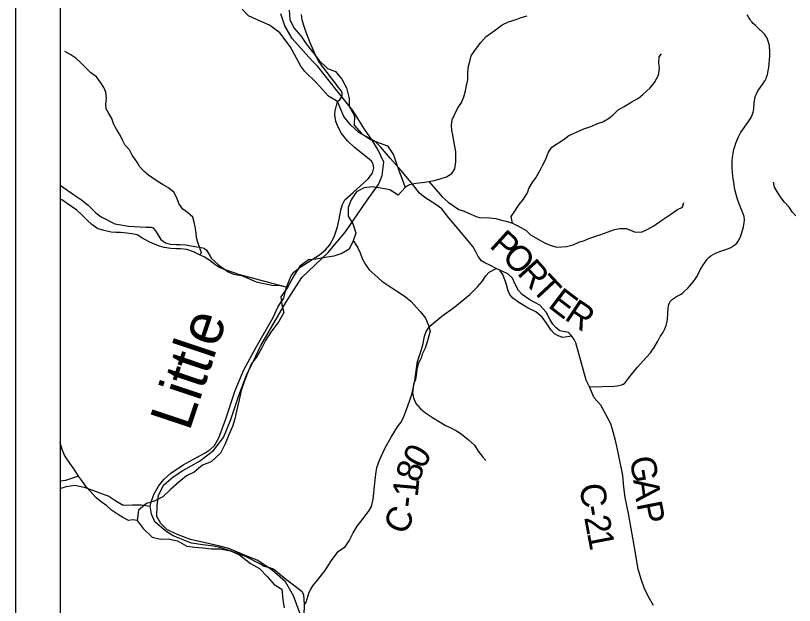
# Model space of a CAD drawing. Extents: x 0 to 34, y 0 to 22.
# Drawn here: x 2 to 3.746, y 17.398 to 18.72 of the extents above; entities that cross this region are included whole.
import ezdxf

# ---------------------------------------------------------------- set-up
doc = ezdxf.new("R2010")
doc.units = 0
for name, color, linetype in [('GM_X_County_Road', 7, 'Continuous'), ('GM_X_County_Road_Text', 7, 'Continuous'), ('GM_X_Minor_River', 7, 'Continuous'), ('GM_X_Minor_River_Text', 7, 'Continuous'), ('GM_X_Rail_Line', 7, 'Continuous'), ('GM_X_Township_Road', 7, 'Continuous'), ('SH_Data', 7, 'Continuous')]:
    doc.layers.add(name, color=color, linetype=linetype)

msp = doc.modelspace()

# ---------------------------------------------------------------- linework, layer by layer
at = {"layer": 'GM_X_County_Road'}
for points in [[(2.7215, 18.5278), (2.7014, 18.5397), (2.6747, 18.5691), (2.6483, 18.5951), (2.6393, 18.6066), (2.6157, 18.6508), (2.5928, 18.6813), (2.569, 18.6989), (2.5402, 18.7113), (2.5221, 18.7197), (2.5078, 18.7347)], [(3.2864, 17.8884), (3.3149, 17.889), (3.3412, 17.8899), (3.3491, 17.8903), (3.3554, 17.8916), (3.3585, 17.8924), (3.3622, 17.894), (3.3658, 17.8968), (3.3704, 17.9024), (3.3751, 17.9086), (3.3935, 17.9312), (3.4144, 17.9544), (3.4234, 17.9642), (3.4257, 17.9679), (3.4316, 17.9762), (3.4397, 17.9902), (3.4453, 18.0012), (3.4457, 18.0018), (3.4511, 18.0093), (3.4556, 18.0184), (3.4586, 18.0256), (3.4604, 18.0319), (3.4611, 18.0355), (3.4615, 18.0383), (3.4626, 18.0533), (3.4633, 18.0643), (3.4637, 18.0689), (3.4645, 18.0729), (3.4658, 18.0766), (3.4677, 18.0791), (3.4699, 18.0819), (3.4732, 18.0847), (3.4821, 18.0903), (3.4921, 18.0959), (3.4963, 18.0992), (3.5008, 18.1031), (3.5069, 18.1094), (3.5128, 18.1156), (3.5189, 18.1232), (3.5237, 18.1295), (3.5278, 18.1363), (3.5357, 18.152), (3.5384, 18.1563), (3.5393, 18.1578), (3.5475, 18.17), (3.5508, 18.1742), (3.5545, 18.1779), (3.5591, 18.1819), (3.5639, 18.1849), (3.5694, 18.1877), (3.5792, 18.1917), (3.5948, 18.197), (3.6037, 18.2007), (3.6129, 18.2063), (3.6172, 18.2102), (3.6202, 18.2145), (3.6227, 18.2198), (3.6259, 18.2266), (3.6323, 18.2464), (3.6338, 18.2562), (3.6341, 18.2626), (3.6332, 18.2699), (3.6315, 18.2756), (3.6281, 18.2834), (3.6238, 18.2943), (3.6206, 18.3022), (3.618, 18.3106), (3.6157, 18.3191), (3.6136, 18.3277), (3.6121, 18.3345), (3.6102, 18.3467), (3.6091, 18.3546), (3.6082, 18.3606), (3.6073, 18.3693), (3.6065, 18.3779), (3.6065, 18.3878), (3.6069, 18.3943), (3.6076, 18.402), (3.6087, 18.4113), (3.6104, 18.4209), (3.6123, 18.4266), (3.6149, 18.4345), (3.6207, 18.4485), (3.6263, 18.4589), (3.6288, 18.4626), (3.6345, 18.4703), (3.6381, 18.475), (3.6419, 18.4802), (3.6462, 18.4869), (3.649, 18.4914), (3.6508, 18.4952), (3.6522, 18.499), (3.6534, 18.5034), (3.6544, 18.507), (3.655, 18.5121), (3.6559, 18.5243), (3.6564, 18.5282), (3.6573, 18.5336), (3.6583, 18.5377), (3.6598, 18.5419), (3.6609, 18.5445), (3.6644, 18.5511), (3.6758, 18.5676), (3.6762, 18.5682), (3.6799, 18.5737), (3.6806, 18.5746), (3.6826, 18.5788), (3.6837, 18.5821), (3.6855, 18.5882), (3.6871, 18.5965), (3.6886, 18.6038), (3.6896, 18.612), (3.6905, 18.6206), (3.6912, 18.6294), (3.6912, 18.6338), (3.6912, 18.6388), (3.6912, 18.6428), (3.6906, 18.6481), (3.69, 18.6528), (3.6896, 18.6551), (3.6882, 18.6606), (3.6862, 18.6671), (3.6842, 18.6708), (3.6823, 18.6738), (3.6795, 18.6777), (3.6763, 18.6814), (3.6715, 18.6859), (3.6703, 18.6869), (3.6587, 18.698), (3.6538, 18.7024), (3.6505, 18.706), (3.6485, 18.7085), (3.6467, 18.7111), (3.6442, 18.715), (3.6422, 18.7185), (3.6403, 18.7218)], [(2.6481, 17.4006), (2.6461, 17.4224), (2.6425, 17.4286), (2.6045, 17.458), (2.5917, 17.4685), (2.5819, 17.4769), (2.576, 17.4805), (2.5701, 17.4823), (2.5635, 17.4842), (2.5572, 17.4855), (2.5488, 17.4906), (2.5156, 17.508), (2.4814, 17.5208), (2.4579, 17.5283), (2.444, 17.531), (2.4199, 17.5342), (2.3948, 17.5379), (2.3536, 17.5545), (2.3371, 17.5647), (2.3125, 17.5855), (2.305, 17.6026), (2.3014, 17.6208), (2.3038, 17.6295), (2.3101, 17.6469), (2.3202, 17.6654), (2.3322, 17.6804), (2.3483, 17.695), (2.3758, 17.7136), (2.4247, 17.7402), (2.4366, 17.748), (2.4462, 17.757), (2.4556, 17.7743), (2.4706, 17.8143), (2.4927, 17.8797), (2.5116, 17.9266), (2.5397, 17.9774), (2.5778, 18.0434), (2.588, 18.0668), (2.593, 18.075), (2.6012, 18.0871), (2.6072, 18.1113), (2.6127, 18.1241), (2.6178, 18.1366), (2.624, 18.1452), (2.6382, 18.1564), (2.6814, 18.1839), (2.6948, 18.1955), (2.7045, 18.2067), (2.7146, 18.2241), (2.7221, 18.2464), (2.7258, 18.2642), (2.7291, 18.2842), (2.7327, 18.2964), (2.7385, 18.3069), (2.7566, 18.3233), (2.7904, 18.3544), (2.8001, 18.3672), (2.8036, 18.3789), (2.8019, 18.3873), (2.7978, 18.3938), (2.7888, 18.4011), (2.7596, 18.4243), (2.7443, 18.4394), (2.7309, 18.4555), (2.7243, 18.4685), (2.7181, 18.4827), (2.7156, 18.4975), (2.7165, 18.507), (2.7215, 18.5278)], [(3.0775, 18.1536), (3.0633, 18.1605), (3.0521, 18.1661), (3.0443, 18.1709), (3.037, 18.1802), (3.032, 18.1906), (3.0251, 18.2026), (3.0075, 18.224), (2.9709, 18.2677), (2.9555, 18.2867), (2.9425, 18.297), (2.9176, 18.3122), (2.9054, 18.322), (2.89, 18.3426), (2.8647, 18.3726), (2.8398, 18.4003), (2.8189, 18.4256), (2.8056, 18.4385), (2.7847, 18.4498), (2.7694, 18.4579), (2.7506, 18.4751), (2.736, 18.4942), (2.7215, 18.5278)], [(2.6481, 17.4006), (2.6518, 17.4055), (2.6586, 17.4281), (2.6613, 17.4334), (2.6667, 17.4425), (2.677, 17.4548), (2.6944, 17.4765), (2.7, 17.4866), (2.7096, 17.5016), (2.7241, 17.5198), (2.7388, 17.5299), (2.7479, 17.5433), (2.7568, 17.5612), (2.7659, 17.5758), (2.7793, 17.5932), (2.7927, 17.6115), (2.7983, 17.6204), (2.8018, 17.6366), (2.8051, 17.6726), (2.8076, 17.6923), (2.8103, 17.7078), (2.8157, 17.7236), (2.8278, 17.7502), (2.8422, 17.7753), (2.8565, 17.7984), (2.8636, 17.8081), (2.8696, 17.8197), (2.8745, 17.8317), (2.8795, 17.8456), (2.8881, 17.8708), (2.8951, 17.9014), (2.8986, 17.9294), (2.9013, 17.9449), (2.9104, 17.972), (2.9138, 17.9855), (2.9166, 18.0018), (2.9203, 18.0123), (2.929, 18.0242), (2.9558, 18.0466), (2.9852, 18.0678), (3.0186, 18.0953), (3.0354, 18.1123), (3.0463, 18.1241), (3.0547, 18.1371), (3.0617, 18.1453), (3.0775, 18.1536)], [(3.4305, 17.3981), (3.419, 17.4174), (3.4093, 17.4378), (3.4034, 17.4551), (3.3962, 17.48), (3.3864, 17.5373), (3.374, 17.6045), (3.3667, 17.6404), (3.3639, 17.6633), (3.3616, 17.6892), (3.3509, 17.741), (3.3455, 17.7651), (3.3401, 17.7877), (3.3347, 17.8054), (3.3224, 17.8278), (3.3118, 17.8468), (3.297, 17.8635), (3.2864, 17.8884), (3.2796, 17.9031), (3.267, 17.9465), (3.2587, 17.9785), (3.256, 17.9866), (3.2523, 17.9945), (3.2474, 18.0021), (3.2269, 17.9987), (3.2168, 18.0024), (3.2082, 18.0069), (3.2005, 18.0154), (3.1903, 18.0306), (3.1805, 18.0441), (3.1668, 18.0559), (3.1496, 18.0648), (3.128, 18.0772), (3.1146, 18.0867), (3.108, 18.0949), (3.1045, 18.1034), (3.0996, 18.1199), (3.0923, 18.1398), (3.0857, 18.1499), (3.0775, 18.1536)], [(2.8377, 17.269), (2.8253, 17.2752), (2.8084, 17.2794), (2.7953, 17.2811), (2.7819, 17.2814), (2.7647, 17.2797), (2.7557, 17.2787), (2.7306, 17.2752), (2.7127, 17.2735), (2.699, 17.2763), (2.6893, 17.2835), (2.6804, 17.2931), (2.6683, 17.3104), (2.6579, 17.3275), (2.654, 17.3383), (2.6469, 17.3614), (2.6466, 17.3675), (2.6469, 17.3761), (2.6481, 17.4006)]]:
    msp.add_lwpolyline(points, dxfattribs=at)
at = {"layer": 'GM_X_Minor_River'}
for points in [[(2.6132, 18.7321), (2.615, 18.7116), (2.6237, 18.6925), (2.6395, 18.6746), (2.6516, 18.6568), (2.6659, 18.6385), (2.681, 18.6191), (2.6992, 18.6015), (2.717, 18.5947), (2.7313, 18.5776), (2.7419, 18.5581), (2.7482, 18.5345), (2.7478, 18.517), (2.7599, 18.4957), (2.7595, 18.4748), (2.7757, 18.4561), (2.7957, 18.4424), (2.8154, 18.4352), (2.8339, 18.4279), (2.8471, 18.4077), (2.8535, 18.3902), (2.8592, 18.3727), (2.8671, 18.3537), (2.8735, 18.3347), (2.8579, 18.3176), (2.8394, 18.3294), (2.8189, 18.3332), (2.8, 18.3366), (2.7815, 18.3344), (2.7644, 18.3249), (2.7523, 18.307), (2.7454, 18.2899), (2.7457, 18.2708), (2.7567, 18.2518), (2.7627, 18.2324), (2.757, 18.2153), (2.7482, 18.1966), (2.7312, 18.1871), (2.7137, 18.1807), (2.694, 18.178), (2.6743, 18.1742), (2.6569, 18.1727), (2.6372, 18.1583), (2.6239, 18.137), (2.6098, 18.1108), (2.5947, 18.0898), (2.5973, 18.0723), (2.6018, 18.0548), (2.5904, 18.0347), (2.5725, 18.0107), (2.56, 17.9924), (2.5512, 17.9742), (2.5417, 17.9567), (2.5284, 17.9388), (2.5201, 17.9187), (2.5128, 17.8996), (2.506, 17.8802), (2.501, 17.8593), (2.4953, 17.8334), (2.4918, 17.8163), (2.4861, 17.7992), (2.4785, 17.7806), (2.4701, 17.7604), (2.4595, 17.7399), (2.4386, 17.7201), (2.4193, 17.7125), (2.4003, 17.6973), (2.3832, 17.6889), (2.3662, 17.6745), (2.3476, 17.6585), (2.3301, 17.6414), (2.3108, 17.6323), (2.2938, 17.6266), (2.2759, 17.6122), (2.2729, 17.589), (2.2857, 17.5711), (2.3061, 17.5516), (2.3246, 17.547), (2.3424, 17.5474)], [(2.8735, 18.3347), (2.8743, 18.3367), (2.8841, 18.3416), (2.8974, 18.3446), (2.9113, 18.3462), (2.9268, 18.3481), (2.9382, 18.3507), (2.9522, 18.3542), (2.9658, 18.3591), (2.9783, 18.3663), (2.9851, 18.377), (2.987, 18.3925), (2.9873, 18.4039), (2.987, 18.4149), (2.9851, 18.4274), (2.9824, 18.4388), (2.9802, 18.4525), (2.9779, 18.4635), (2.9771, 18.4737), (2.9787, 18.4863), (2.9836, 18.4961), (2.9911, 18.5121), (2.9995, 18.525), (3.0048, 18.5379), (3.0085, 18.5512), (3.0112, 18.5633), (3.0138, 18.5762), (3.0142, 18.5922), (3.0157, 18.6066), (3.0191, 18.6202), (3.0218, 18.6297), (3.0312, 18.6438), (3.0433, 18.6601), (3.0551, 18.6734), (3.0679, 18.6818), (3.0811, 18.692), (3.0913, 18.6992), (3.105, 18.7061), (3.122, 18.711), (3.1337, 18.7156), (3.1469, 18.7198)], [(2.4127, 18.1842), (2.4169, 18.1887), (2.4127, 18.2016), (2.4086, 18.2119), (2.4055, 18.2229), (2.4048, 18.2331), (2.4025, 18.2468), (2.4006, 18.2571), (2.3972, 18.2681), (2.3851, 18.2791), (2.3753, 18.2866), (2.3662, 18.2992), (2.3617, 18.3117), (2.3549, 18.3242), (2.3417, 18.3352), (2.3311, 18.3405), (2.3198, 18.3473), (2.308, 18.3557), (2.2982, 18.3625), (2.2873, 18.3716), (2.2789, 18.3815), (2.2725, 18.3917), (2.2616, 18.4073), (2.2555, 18.4194), (2.2449, 18.4308), (2.2396, 18.441), (2.2343, 18.4524), (2.2272, 18.4642), (2.2204, 18.4763), (2.2155, 18.4892), (2.209, 18.501), (2.2034, 18.5108), (2.2022, 18.5207), (2.2037, 18.5351), (2.2022, 18.5484), (2.1981, 18.559), (2.1913, 18.5693), (2.1818, 18.5829), (2.169, 18.592), (2.1584, 18.6019), (2.1452, 18.6148), (2.135, 18.6246), (2.1236, 18.6318), (2.1108, 18.6398)], [(3.1143, 18.2552), (3.1109, 18.2696), (3.1181, 18.2795), (3.1287, 18.297), (3.1385, 18.3084), (3.1476, 18.3228), (3.1506, 18.3323), (3.1582, 18.3452), (3.1665, 18.3562), (3.176, 18.3737), (3.1816, 18.3843), (3.1884, 18.3972), (3.1945, 18.4139), (3.2024, 18.4249), (3.2296, 18.4435), (3.2402, 18.4515), (3.2588, 18.4595), (3.2743, 18.4663), (3.292, 18.4724), (3.3049, 18.4781), (3.317, 18.4823), (3.3294, 18.4895), (3.3393, 18.4971), (3.3514, 18.5089), (3.3642, 18.5161), (3.3816, 18.5267), (3.3964, 18.5351), (3.4062, 18.5431), (3.4228, 18.5583), (3.4323, 18.5704), (3.4417, 18.5864), (3.444, 18.6019), (3.4425, 18.6141), (3.4433, 18.6277), (3.4482, 18.6346)], [(2.9268, 18.3481), (2.9567, 18.3136), (2.9699, 18.3022), (2.9816, 18.2938), (2.9941, 18.2859), (3.0058, 18.2821), (3.0157, 18.2775), (3.0323, 18.27), (3.0421, 18.2669), (3.0565, 18.2677), (3.0765, 18.2654), (3.0894, 18.2616), (3.0996, 18.2594), (3.1143, 18.2552), (3.126, 18.2488), (3.1449, 18.2385), (3.1544, 18.2287), (3.1714, 18.2188), (3.1873, 18.2105), (3.2005, 18.2048), (3.2137, 18.2014), (3.2247, 18.2021), (3.2353, 18.2029), (3.25, 18.2063), (3.2632, 18.212), (3.2757, 18.2158), (3.2855, 18.2204), (3.3007, 18.2257), (3.3124, 18.2299), (3.3286, 18.2352), (3.3426, 18.2405), (3.3544, 18.2432), (3.3691, 18.2432), (3.3789, 18.2394), (3.3891, 18.2349), (3.405, 18.2357), (3.416, 18.2406), (3.4307, 18.249), (3.4492, 18.2619), (3.4689, 18.2752), (3.484, 18.2854), (3.4954, 18.2911), (3.4984, 18.301)], [(3.749, 18.2712), (3.7414, 18.2806), (3.7346, 18.2909), (3.7241, 18.3019), (3.7165, 18.3114), (3.7108, 18.3209), (3.7018, 18.3353), (3.6991, 18.347)], [(2.6086, 18.1111), (2.5004, 18.1402), (2.4857, 18.1448), (2.4698, 18.1504), (2.4573, 18.1558), (2.4467, 18.1626), (2.4361, 18.1709), (2.4241, 18.1789), (2.4127, 18.1842), (2.3987, 18.1906), (2.3836, 18.1963), (2.37, 18.1978), (2.3594, 18.1978), (2.3481, 18.1982), (2.3333, 18.2001), (2.3224, 18.2035), (2.3095, 18.2084), (2.2982, 18.2137), (2.2834, 18.2224), (2.2729, 18.2289), (2.2604, 18.2308), (2.2498, 18.2323), (2.2351, 18.2342), (2.2252, 18.2342), (2.2143, 18.2349), (2.1988, 18.2387), (2.1844, 18.2425), (2.1708, 18.252), (2.1602, 18.2618), (2.1477, 18.274), (2.1372, 18.2838), (2.1254, 18.2926), (2.1035, 18.307), (2.1, 18.3084)], [(2.757, 18.2153), (2.7586, 18.2136), (2.7677, 18.2), (2.7726, 18.1886), (2.7771, 18.1761), (2.7847, 18.162), (2.793, 18.1503), (2.8058, 18.1393), (2.821, 18.1248), (2.8327, 18.1173), (2.8436, 18.1097), (2.8576, 18.101), (2.8739, 18.0896), (2.8867, 18.0793), (2.8988, 18.0661), (2.9075, 18.0566), (2.9192, 18.0418), (2.9253, 18.0277), (2.9294, 18.0126), (2.9256, 17.9993), (2.9211, 17.9841), (2.9185, 17.9746), (2.9116, 17.9617), (2.909, 17.9522), (2.9037, 17.9419), (2.8999, 17.9279), (2.898, 17.9146), (2.8969, 17.9047), (2.8924, 17.8941), (2.8901, 17.8748), (2.8924, 17.8634), (2.8976, 17.8512), (2.9082, 17.8387), (2.9192, 17.8296), (2.9351, 17.8194), (2.9517, 17.8091), (2.9642, 17.8015), (2.974, 17.797), (2.9884, 17.7898), (2.9989, 17.783), (3.0148, 17.7701), (3.0288, 17.7572), (3.0371, 17.7439), (3.0477, 17.731), (3.0544, 17.7234)], [(2.2729, 17.589), (2.2629, 17.5905), (2.2531, 17.5886), (2.2402, 17.5958), (2.2285, 17.603), (2.2153, 17.6117), (2.2047, 17.6216), (2.1922, 17.6307), (2.1801, 17.6406), (2.168, 17.6535), (2.1593, 17.6637), (2.1499, 17.6762), (2.1412, 17.6884), (2.1325, 17.7013), (2.1253, 17.7123), (2.1163, 17.7248), (2.1098, 17.735), (2.1045, 17.7475), (2.1008, 17.7608), (2.1, 17.7642)], [(2.1412, 17.6884), (2.1117, 17.6781), (2.1015, 17.6766), (2.1, 17.6763)], [(2.3424, 17.5474), (2.3628, 17.5432), (2.3836, 17.531), (2.4022, 17.5287), (2.4196, 17.5272), (2.4389, 17.5253), (2.4578, 17.5252), (2.482, 17.521), (2.5021, 17.5119), (2.5267, 17.4921), (2.5467, 17.481), (2.5641, 17.4635), (2.5795, 17.4456), (2.5973, 17.4346), (2.5991, 17.411), (2.6021, 17.3931)]]:
    msp.add_lwpolyline(points, dxfattribs=at)
at = {"layer": 'GM_X_Rail_Line'}
msp.add_lwpolyline([(2.6383, 17.3794), (2.6229, 17.4196), (2.605, 17.4511), (2.5756, 17.4771), (2.5435, 17.4991), (2.5119, 17.512), (2.4784, 17.5259), (2.4577, 17.5315), (2.4223, 17.5394), (2.3925, 17.5461), (2.3605, 17.5579), (2.3392, 17.5683), (2.3253, 17.5819), (2.3165, 17.5975), (2.3173, 17.6224), (2.3205, 17.6458), (2.3323, 17.6689), (2.3532, 17.6866), (2.3753, 17.7006), (2.4123, 17.7213), (2.4437, 17.7458), (2.466, 17.7747), (2.4829, 17.8148), (2.5008, 17.8685), (2.5185, 17.9165), (2.533, 17.9439), (2.5497, 17.9808), (2.606, 18.0774), (2.6421, 18.133), (2.7012, 18.1892), (2.7396, 18.2353), (2.7869, 18.3045), (2.8136, 18.3416), (2.8221, 18.3615), (2.8253, 18.3919), (2.812, 18.4203), (2.7994, 18.4407), (2.7822, 18.4656), (2.7559, 18.5076), (2.7201, 18.5523), (2.6775, 18.6058), (2.6664, 18.6171), (2.6506, 18.634), (2.6202, 18.6687), (2.6037, 18.697), (2.5949, 18.7243)], dxfattribs=at)
at = {"layer": 'GM_X_Township_Road'}
for points in [[(2.7215, 18.5278), (2.7274, 18.5328), (2.7311, 18.5376), (2.7326, 18.5413), (2.7326, 18.546), (2.7305, 18.5504), (2.7278, 18.5546), (2.7221, 18.5616), (2.7188, 18.5661), (2.6856, 18.6092), (2.6792, 18.6188), (2.6733, 18.6302), (2.6607, 18.6591), (2.6507, 18.6842), (2.6461, 18.6978), (2.6427, 18.7102), (2.6409, 18.7224)], [(2.1, 18.3405), (2.1003, 18.3402), (2.1322, 18.3177), (2.1476, 18.3072), (2.1626, 18.2952), (2.1801, 18.2779), (2.1917, 18.269), (2.2229, 18.2537), (2.2535, 18.2479), (2.2925, 18.2458), (2.3039, 18.246), (2.3084, 18.2445), (2.3151, 18.2356), (2.3258, 18.2184), (2.3363, 18.211), (2.3469, 18.2078), (2.3597, 18.2072), (2.3692, 18.2075), (2.3817, 18.2062), (2.4017, 18.2028), (2.4161, 18.2007), (2.4229, 18.1991), (2.4281, 18.1945), (2.434, 18.1845), (2.4392, 18.1757), (2.456, 18.161), (2.4763, 18.1459), (2.4887, 18.1404), (2.5064, 18.1375), (2.5208, 18.1319), (2.5396, 18.1233), (2.5743, 18.1163), (2.5955, 18.1149), (2.6072, 18.1113)], [(3.2474, 18.0021), (3.24, 18.0102), (3.2205, 18.0137), (3.2113, 18.0208), (3.2043, 18.0286), (3.1978, 18.0395), (3.1895, 18.0557), (3.1756, 18.0709), (3.1528, 18.0833), (3.1357, 18.0952), (3.1276, 18.1038), (3.1197, 18.12), (3.114, 18.132), (3.1037, 18.1414), (3.0857, 18.1499)], [(2.1, 17.6607), (2.1133, 17.6646), (2.1327, 17.6677), (2.1535, 17.6633), (2.181, 17.6537), (2.2092, 17.6431), (2.225, 17.633), (2.2415, 17.6232), (2.262, 17.6241), (2.2813, 17.6242), (2.3014, 17.6208)]]:
    msp.add_lwpolyline(points, dxfattribs=at)
at = {"layer": 'SH_Data'}
for p, q in [((2, 21), (2, 14)), ((2.1, 20.9), (2.1, 14.1))]:
    msp.add_line(p, q, dxfattribs=at)

# ---------------------------------------------------------------- texts
at = {"layer": 'GM_X_County_Road_Text'}
for s, rotation, p in [('P', 317.693, (3.0603, 18.2024)), ('O', 314.3097, (3.088, 18.1772)), ('R', 312.0325, (3.1226, 18.1419)), ('T', 313.018, (3.1545, 18.1064)), ('E', 322.7069, (3.1913, 18.0683)), ('R', 326.0916, (3.2281, 18.0404)), ('0', 60.7773, (2.9145, 17.7018)), ('G', 279.4927, (3.3766, 17.7285)), ('8', 70.8212, (2.904, 17.6711)), ('1', 84.7104, (2.9016, 17.6398)), ('A', 277.7242, (3.3847, 17.6796)), ('C', 276.7483, (3.2647, 17.669)), ('-', 83.5897, (2.8988, 17.6154)), ('C', 64.7071, (2.8733, 17.5537)), ('-', 279.5736, (3.2706, 17.6196)), ('P', 280.9768, (3.392, 17.6266)), ('2', 280.4943, (3.2747, 17.5956)), ('1', 280.8308, (3.2811, 17.5608))]:
    msp.add_text(s, height=0.0568, rotation=rotation, dxfattribs=at).set_placement(p)
at = {"layer": 'GM_X_Minor_River_Text'}
msp.add_text('Little', height=0.09475, rotation=71.5031, dxfattribs=at).set_placement((2.3895, 17.7866))

doc.saveas('drawing.dxf')
